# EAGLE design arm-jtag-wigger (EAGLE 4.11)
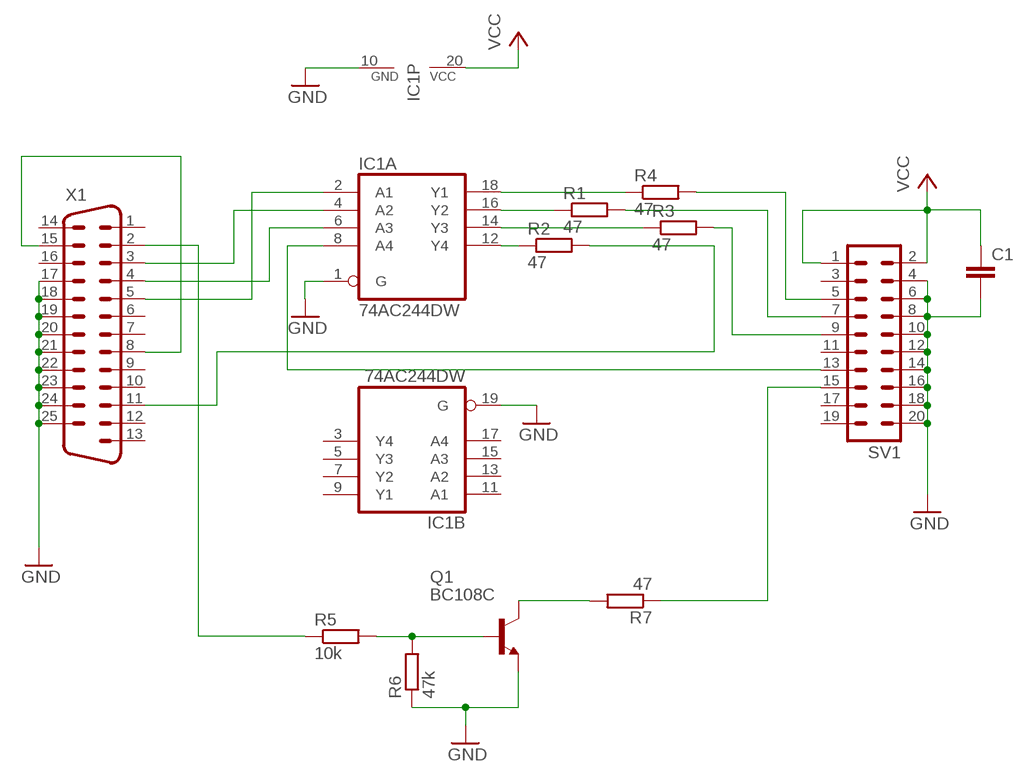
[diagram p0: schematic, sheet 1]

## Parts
C1  C-EU050-024X044  [C050-024X044]
IC1  74AC244DW  [SO20W]
Q1  BC108C  [TO18]
R1  47  R-EU_0207/10  [0207/10]
R2  47  R-EU_0207/10  [0207/10]
R3  47  R-EU_0207/10  [0207/10]
R4  47  R-EU_0207/10  [0207/10]
R5  10k  R-EU_0207/10  [0207/10]
R6  47k  R-EU_0207/10  [0207/10]
R7  47  R-EU_0207/10  [0207/10]
SV1  ML20  [ML20]
X1  M25HP  [M25HP]

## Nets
GND: C1.2 IC1.1(A:G) IC1.10(P:GND) IC1.19(B:G) Q1.1(E) R6.1 SV1.4 SV1.6 SV1.8 SV1.10 SV1.12 SV1.14 SV1.16 SV1.18 SV1.20 X1.17 X1.18 X1.19 X1.20 X1.21 X1.22 X1.23 X1.24 X1.25
N$1: IC1.8(A:A4) SV1.13
N$2: X1.8 X1.15
N$5: R7.1 SV1.15
N$6: Q1.3(C) R7.2
N$7: Q1.2(B) R5.2 R6.2
N$8: R5.1 X1.2
N$9: IC1.18(A:Y1) R4.1
N$10: IC1.16(A:Y2) R1.1
N$11: IC1.14(A:Y3) R3.1
N$12: IC1.12(A:Y4) R2.1
N$13: R4.2 SV1.5
N$14: R1.2 SV1.7
N$15: R3.2 SV1.9
N$16: R2.2 X1.11
N$17: IC1.2(A:A1) X1.5
N$18: IC1.4(A:A2) X1.3
N$19: IC1.6(A:A3) X1.4
VCC: C1.1 IC1.20(P:VCC) SV1.1 SV1.2
Unconnected: IC1.3(B:Y4) IC1.5(B:Y3) IC1.7(B:Y2) IC1.9(B:Y1) IC1.11(B:A1) IC1.13(B:A2) IC1.15(B:A3) IC1.17(B:A4) SV1.3 SV1.11 SV1.17 SV1.19 X1.1 X1.6 X1.7 X1.9 X1.10 X1.12 X1.13 X1.14 X1.16

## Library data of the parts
C1 = rcl:C-EU: CAPACITOR, European symbol
IC1 = 74xx-eu:74*244: Octal BUFFER and LINE DRIVER, 3-state
Q1 = transistor-npn:BC108C: NPN Transistor
R1-R7 = rcl:R-EU_: RESISTOR, European symbol
SV1 = con-harting-ml:ML20: HARTING
X1 = con-subd:M25: SUB-D

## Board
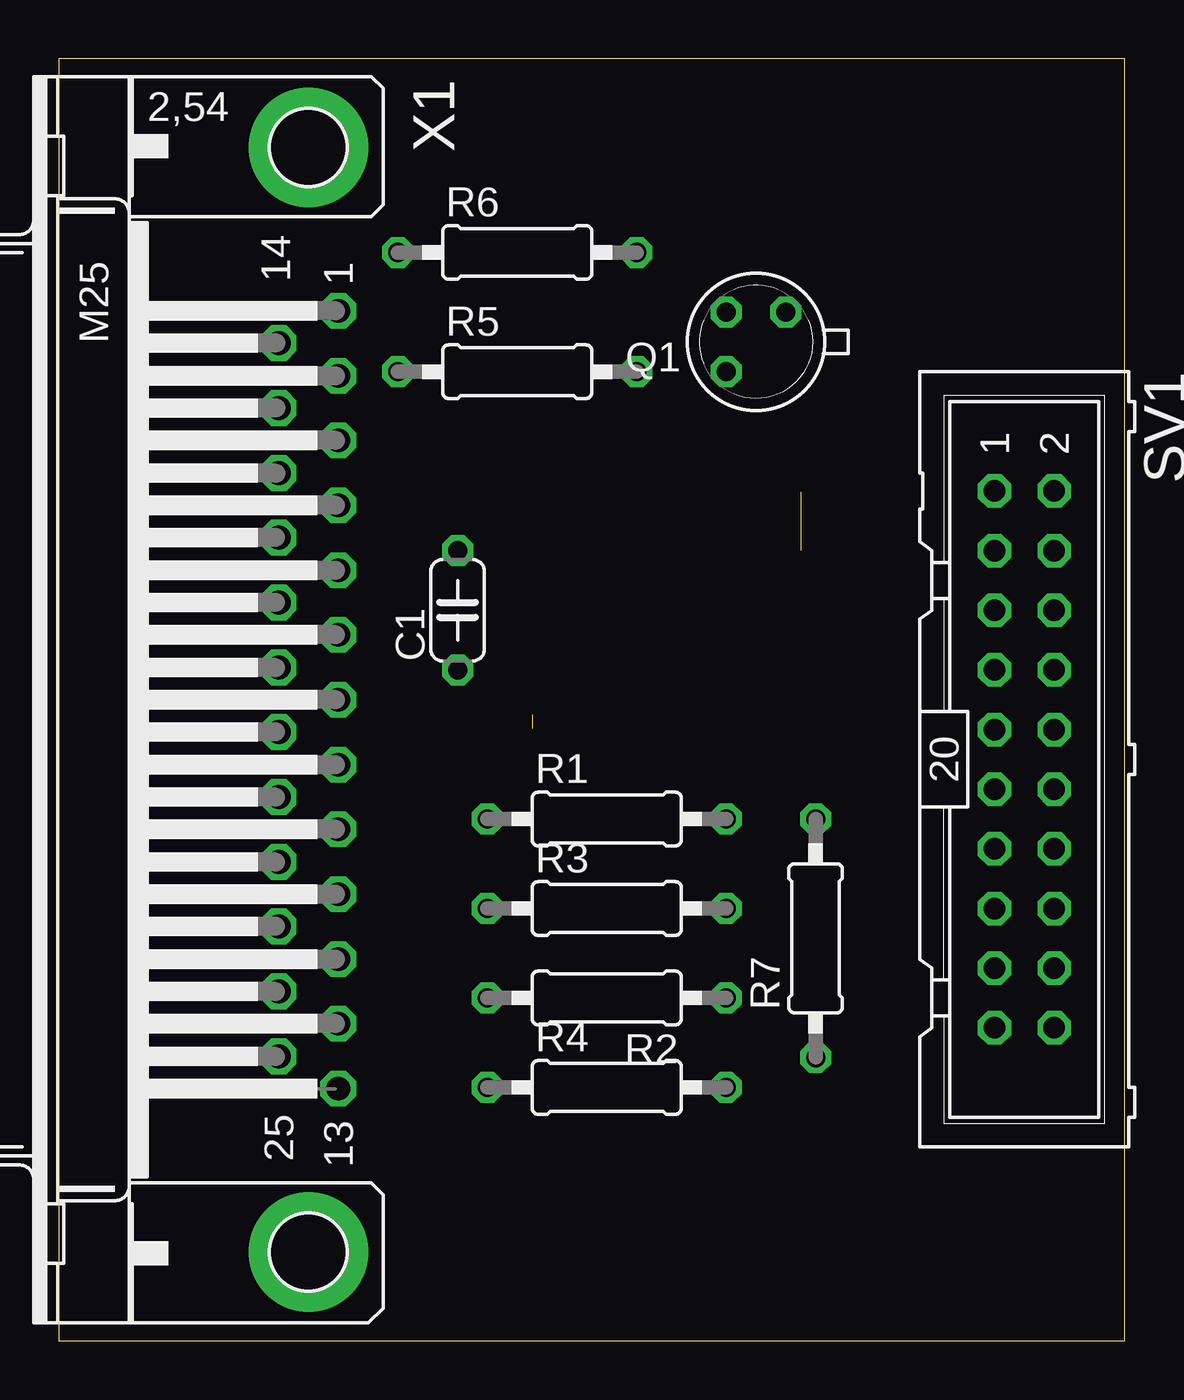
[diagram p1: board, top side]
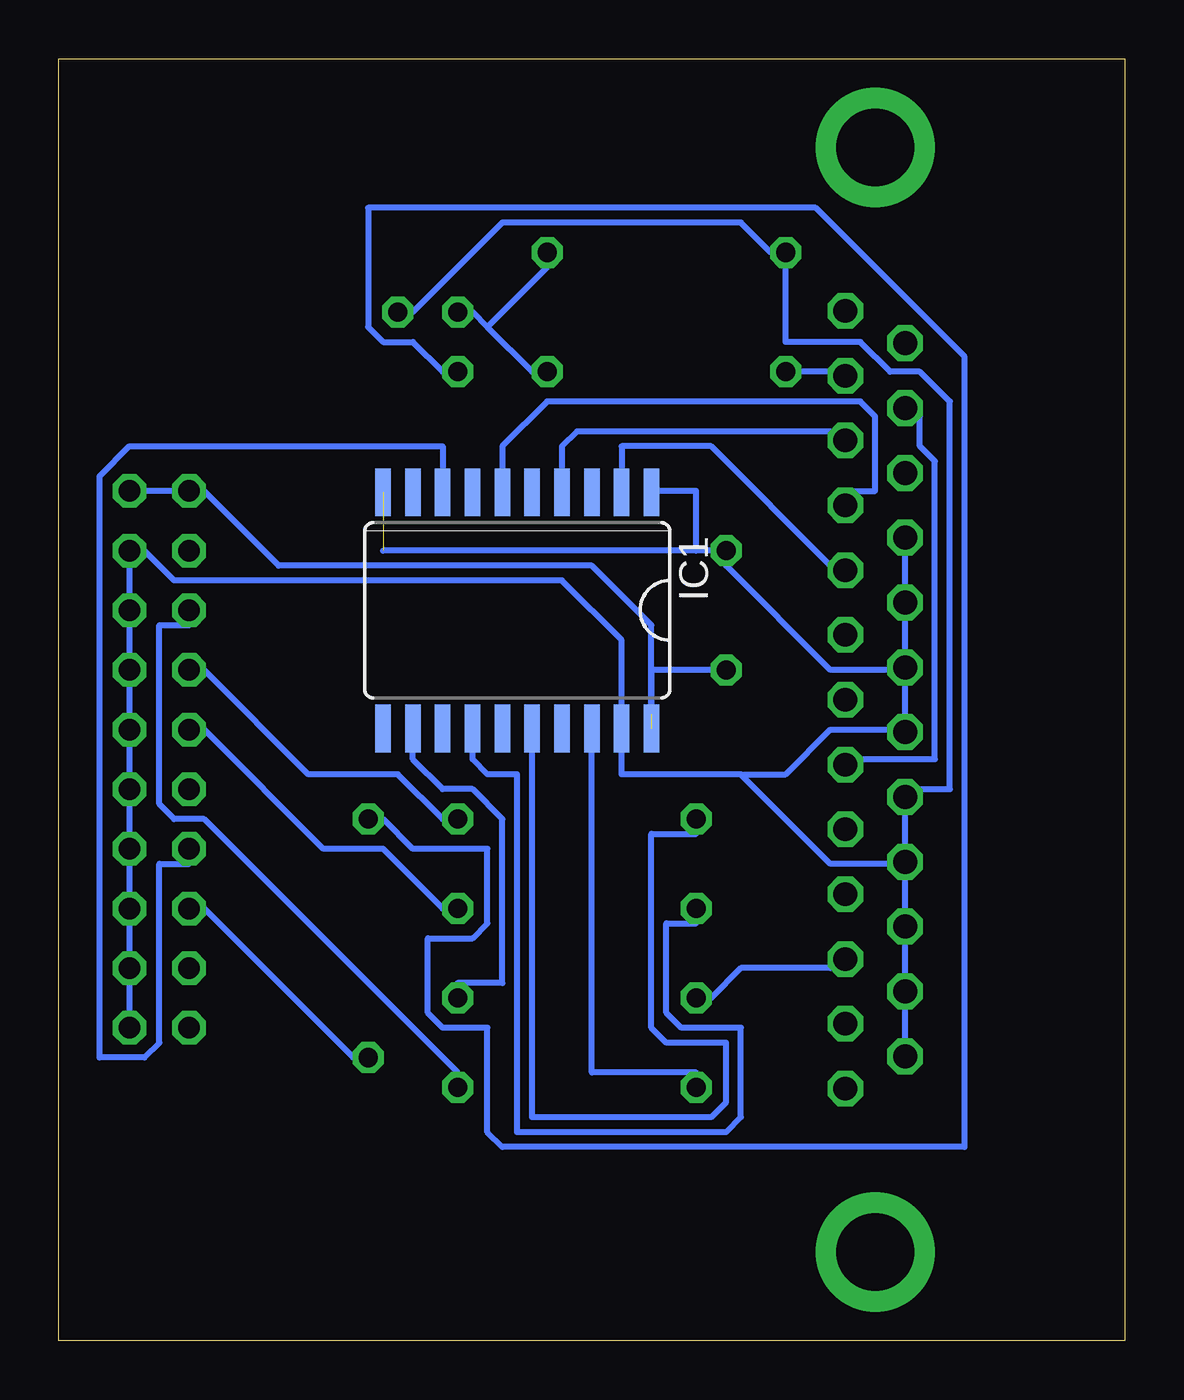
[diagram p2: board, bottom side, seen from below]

Size 45.39 x 54.6 mm. Coordinates in mm from the lower left corner, seen from the top.
Outline: 0,0 45.39,0 45.39,54.6 0,54.6 0,0
Copper layers (1*16): Top 0.035mm / dielectric 1.5mm / Bottom 0.035mm
Design rules "default": minimum track width 10mil, minimum drill 24mil, track to track 8mil, track to pad 8mil, pad to pad 8mil, via to via 8mil, smd to smd 8mil, copper to edge 40mil, drill to drill 8mil, minimum pad ring 10mil, minimum via ring 8mil, stop-mask expansion 4mil, vias tented up to drill 0mil, thermal gap 10mil

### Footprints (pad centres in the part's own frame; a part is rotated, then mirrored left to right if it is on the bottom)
C050-024X044 = drill 0.813 octagon: 1 -2.54,0; 2 2.54,0
SO20W = smd 0.66 x 2.032: 1 -5.715,-5.029; 2 -4.445,-5.029; 3 -3.175,-5.029; 4 -1.905,-5.029; 5 -0.635,-5.029; 6 0.635,-5.029; 7 1.905,-5.029; 8 3.175,-5.029; 9 4.445,-5.029; 10 5.715,-5.029; 11 5.715,5.029; 12 4.445,5.029; 13 3.175,5.029; 14 1.905,5.029; 15 0.635,5.029; 16 -0.635,5.029; 17 -1.905,5.029; 18 -3.175,5.029; 19 -4.445,5.029; 20 -5.715,5.029
TO18 = drill 0.813 octagon: 1 -1.27,-1.27; 2 1.27,-1.27; 3 1.27,1.27
0207/10 = drill 0.813 octagon: 1 -5.08,0; 2 5.08,0
ML20 = drill 0.914 octagon: 1 -11.43,-1.27; 2 -11.43,1.27; 3 -8.89,-1.27; 4 -8.89,1.27; 5 -6.35,-1.27; 6 -6.35,1.27; 7 -3.81,-1.27; 8 -3.81,1.27; 9 -1.27,-1.27; 10 -1.27,1.27; 11 1.27,-1.27; 12 1.27,1.27; 13 3.81,-1.27; 14 3.81,1.27; 15 6.35,-1.27; 16 6.35,1.27; 17 8.89,-1.27; 18 8.89,1.27; 19 11.43,-1.27; 20 11.43,1.27
M25HP = drill 1.016 octagon: 1 -16.561,1.27; 2 -13.792,1.27; 3 -11.049,1.27; 4 -8.28,1.27; 5 -5.512,1.27; 6 -2.769,1.27; 7 0,1.27; 8 2.769,1.27; 9 5.512,1.27; 10 8.28,1.27; 11 11.049,1.27; 12 13.792,1.27; 13 16.561,1.27; 14 -15.189,-1.27; 15 -12.421,-1.27; 16 -9.652,-1.27; 17 -6.909,-1.27; 18 -4.14,-1.27; 19 -1.372,-1.27; 20 1.372,-1.27; 21 4.14,-1.27; 22 6.909,-1.27; 23 9.652,-1.27; 24 12.421,-1.27; 25 15.189,-1.27 | drill 3.302 pad 5.08 round: G1 -23.52,0; G2 23.52,0

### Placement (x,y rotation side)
C1  16.98,31.11 90 top
IC1  25.87,31.11 180 bottom
Q1  29.68,42.54 180 top
R1  23.33,22.22 0 top
R2  23.33,14.6 180 top
R3  23.33,18.41 0 top
R4  23.33,10.79 0 top
R5  19.52,41.27 0 top
R6  19.52,46.35 0 top
R7  32.22,17.14 90 top
SV1  41.11,24.76 270 top
X1  10.63,27.3 270 top

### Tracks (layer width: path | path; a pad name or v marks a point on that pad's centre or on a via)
GND  (1 unrouted)
  Bottom 0.254: SV1.20 SV1.18 SV1.16 SV1.14 SV1.12 SV1.10 SV1.8 SV1.6 SV1.4 41.74,33.65 40.48,32.38 23.96,32.38 21.42,29.84 IC1.19 21.42,24.12 16.34,24.12 | Q1.1 30.31,43.81 26.5,47.62 16.34,47.62 15.08,46.35 R6.1 14.44,42.54 11.27,42.54 10,41.27 8.73,41.27 7.46,40 7.46,23.49 8.73,23.49 X1.21 X1.22 | 18.25,33.65 18.25,36.19 20.15,36.19 IC1.1 | 18.25,33.65 C1.2 16.98,33.02 12.54,28.57 10,28.57 X1.19 | 18.25,33.65 31.58,33.65 | X1.25 X1.24 X1.23 X1.22 | 16.34,24.12 14.44,24.12 12.54,26.03 10,26.03 X1.20 X1.19 | X1.19 X1.18 X1.17 | 16.34,24.12 12.54,20.31 10,20.31 X1.22
N$1
  Bottom 0.254: IC1.8 29.04,38.1 42.38,38.1 43.65,36.83 43.65,12.06 41.74,12.06 41.11,12.7 41.11,20.31 39.84,20.31 SV1.13
N$2
  Bottom 0.254: X1.15 8.73,39.37 8.73,38.1 8.09,37.46 8.09,24.76 11.27,24.76 X1.8
N$5
  Bottom 0.254: R7.1 32.85,12.06 39.2,18.41 SV1.15
N$6
  Bottom 0.254: Q1.3 29.04,41.27 30.31,42.54 31.58,42.54 32.22,43.18 32.22,48.26 13.17,48.26 6.82,41.91 6.82,8.25 26.5,8.25 27.14,8.89 27.14,13.33 29.04,13.33 29.68,13.97 29.68,17.14 27.77,17.14 27.14,17.77 27.14,20.95 30.31,20.95 31.58,22.22 R7.2
N$7
  Bottom 0.254: 27.14,43.18 27.77,43.81 Q1.2 | 27.14,43.18 25.23,41.27 R5.2 | 27.14,43.18 24.6,45.72 R6.2
N$8
  Bottom 0.254: R5.1 12.54,41.27 X1.2
N$9
  Bottom 0.254: IC1.18 22.7,11.43 18.25,11.43 R4.1
N$10
  Bottom 0.254: IC1.16 25.23,9.52 17.61,9.52 16.98,10.16 16.98,12.7 19.52,12.7 20.15,13.33 20.15,21.58 18.25,21.58 R1.1
N$11
  Bottom 0.254: IC1.14 27.77,24.76 27.14,24.12 25.87,24.12 25.87,8.89 16.98,8.89 16.34,9.52 16.34,13.33 18.88,13.33 19.52,13.97 19.52,17.77 18.25,17.77 R3.1
N$12
  Bottom 0.254: IC1.12 30.31,24.76 29.04,23.49 27.77,23.49 26.5,22.22 26.5,15.24 28.41,15.24 R2.1
N$13
  Bottom 0.254: R4.2 28.41,11.43 39.2,22.22 40.48,22.22 41.11,22.86 41.11,30.47 39.84,30.47 SV1.5
N$14
  Bottom 0.254: R1.2 29.04,22.22 30.95,24.12 34.76,24.12 39.2,28.57 SV1.7
N$15
  Bottom 0.254: R3.2 29.04,18.41 31.58,20.95 34.12,20.95 39.2,26.03 SV1.9
N$16
  Bottom 0.254: R2.2 17.61,14.6 16.34,15.87 12.54,15.87 X1.11
N$17
  Bottom 0.254: IC1.2 21.42,38.1 17.61,38.1 12.54,33.02 X1.5
N$18
  Bottom 0.254: IC1.4 23.96,38.1 23.33,38.73 12.54,38.73 X1.3
N$19
  Bottom 0.254: IC1.6 26.5,38.1 24.6,40 11.27,40 10.63,39.37 10.63,36.19 11.9,36.19 X1.4
VCC  (1 unrouted)
  Bottom 0.254: SV1.2 SV1.1 39.2,36.19 36.03,33.02 22.7,33.02 20.15,30.47 20.15,26.66 20.15,28.57 C1.1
